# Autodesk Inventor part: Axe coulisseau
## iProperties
Author: Flavien MARTY
Shininess: 86.0
PropertySet Name: _Private Model Information
Created: 2001-10
Part Number: Axe coulisseau
Material: Par défaut
Document SubType Name: Modélisation
Designer: Flavien MARTY
Control State: 0
Master: False
Checked Out: False
PropertySet Name: Design Tracking Control
Density: 0.0
Volumn: 0.0
Area: 0.0
PropertySet Name: Model Information
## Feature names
1. Base1
